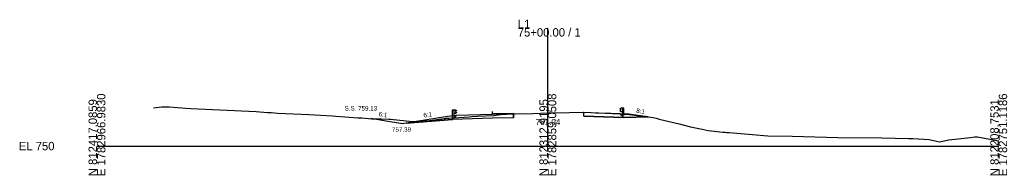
# Model space of a CAD drawing. Extents: x 5574 to 10203, y -10 to 9546.
# Drawn here: x 8574.3 to 8902.8, y 2990.3 to 3042 of the extents above; entities that cross this region are included whole.
import ezdxf

# ---------------------------------------------------------------- set-up
doc = ezdxf.new("R2010")
doc.units = 0
for name, color, linetype in [('Exist Cross Section Cell', 7, 'Continuous'), ('Exist XS Center Line Elevation Label', 7, 'Continuous'), ('Exist XS Ground Line', 7, 'Continuous'), ('Prop XS Ditch Slope Text', 7, 'Continuous'), ('Prop XS Ditch Standard Text', 7, 'Continuous'), ('Prop XS Dump Level', 7, 'Continuous'), ('Prop XS Earthwork Shape', 7, 'Continuous'), ('Prop XS EOT Tick Mark', 7, 'Continuous'), ('Prop XS Finish Grade', 7, 'Continuous'), ('Prop XS Finish Grade Earthwork', 7, 'Continuous'), ('Prop XS Finish Grade Paved Shoulder', 7, 'Continuous'), ('Prop XS Finish Grade Pavement', 7, 'Continuous'), ('Prop XS Guardrail', 7, 'Continuous'), ('Prop XS Hydro Typical Ditch Data', 7, 'Continuous'), ('Prop XS Pvmt Edge Slope', 7, 'Continuous'), ('Prop XS Side Slope Text', 7, 'Continuous'), ('Prop XS SS Elevation Text', 7, 'Continuous'), ('Prop XS Subgrade Earthwork', 7, 'Continuous'), ('Scratch_Level_3', 7, 'Continuous'), ('Scratch_Level_6', 7, 'Continuous')]:
    doc.layers.add(name, color=color, linetype=linetype)

msp = doc.modelspace()

# ---------------------------------------------------------------- linework, layer by layer
at = {"layer": 'Exist Cross Section Cell'}
for p, q in [((8750, 3000), (8750, 3039.22)), ((8600, 3000), (8750, 3000)), ((8750, 3000), (8900, 3000))]:
    msp.add_line(p, q, dxfattribs=at)
at = {"layer": 'Exist XS Ground Line'}
for p, q in [((8618.81, 3012.75), (8621.53, 3013.06)), ((8621.53, 3013.06), (8624.02, 3013.07)), ((8624.02, 3013.07), (8629.6, 3012.65)), ((8629.6, 3012.65), (8631.2, 3012.56)), ((8631.2, 3012.56), (8652.98, 3011.55)), ((8652.98, 3011.55), (8656.75, 3011.16)), ((8656.75, 3011.16), (8657.95, 3011.14)), ((8657.95, 3011.14), (8660.18, 3010.98)), ((8660.18, 3010.98), (8670.51, 3010.47)), ((8670.51, 3010.47), (8678.36, 3010.07)), ((8678.36, 3010.07), (8679.51, 3009.95)), ((8679.51, 3009.95), (8682.41, 3009.77)), ((8682.41, 3009.77), (8686.75, 3009.4)), ((8686.75, 3009.4), (8688.09, 3009.35)), ((8717.11, 3009.32), (8723.79, 3009.73)), ((8723.79, 3009.73), (8724.75, 3009.79)), ((8724.75, 3009.79), (8726.55, 3009.92)), ((8726.55, 3009.92), (8732.01, 3010.22)), ((8732.01, 3010.22), (8734.27, 3010.48)), ((8734.27, 3010.48), (8736.3, 3010.58)), ((8736.3, 3010.58), (8738.53, 3010.69)), ((8738.53, 3010.69), (8745, 3010.89)), ((8745, 3010.89), (8750, 3011.04)), ((8750, 3011.04), (8750.89, 3011.07)), ((8750.89, 3011.07), (8757.25, 3011.18)), ((8757.25, 3011.18), (8761.88, 3011.26)), ((8761.88, 3011.26), (8764.28, 3011.16)), ((8764.28, 3011.16), (8765.87, 3011.09)), ((8765.87, 3011.09), (8770.93, 3010.94)), ((8770.93, 3010.94), (8776.99, 3010.75)), ((8776.99, 3010.75), (8780.82, 3010.14)), ((8780.82, 3010.14), (8783.35, 3009.74)), ((8783.35, 3009.74), (8785.09, 3009.47)), ((8785.09, 3009.47), (8786.01, 3009.27)), ((8688.09, 3009.35), (8691.47, 3009.11)), ((8691.47, 3009.11), (8694.53, 3009.08)), ((8694.53, 3009.08), (8697.1, 3008.96)), ((8697.1, 3008.96), (8697.63, 3008.93)), ((8697.63, 3008.93), (8705.02, 3008.2)), ((8705.02, 3008.2), (8706.15, 3008.28)), ((8706.15, 3008.28), (8710.65, 3008.48)), ((8710.65, 3008.48), (8715.53, 3009.16)), ((8715.53, 3009.16), (8715.87, 3009.2)), ((8715.87, 3009.2), (8716.22, 3009.26)), ((8716.22, 3009.26), (8717.11, 3009.32)), ((8786.01, 3009.27), (8787, 3009)), ((8787, 3009), (8793.7, 3007.43)), ((8793.7, 3007.43), (8797.44, 3006.36)), ((8797.44, 3006.36), (8801.32, 3005.62)), ((8801.32, 3005.62), (8803.31, 3005.18)), ((8803.31, 3005.18), (8808.19, 3004.67)), ((8808.19, 3004.67), (8808.96, 3004.64)), ((8808.96, 3004.64), (8809.49, 3004.55)), ((8809.49, 3004.55), (8810.27, 3004.48)), ((8810.27, 3004.48), (8823.15, 3003.45)), ((8823.15, 3003.45), (8831.28, 3003.28)), ((8831.28, 3003.28), (8846.52, 3002.83)), ((8846.52, 3002.83), (8861.15, 3002.73)), ((8883.46, 3002.09), (8890.57, 3002.83)), ((8890.57, 3002.83), (8892, 3003.09)), ((8892, 3003.09), (8892.9, 3003.11)), ((8892.9, 3003.11), (8899.36, 3001.91)), ((8861.15, 3002.73), (8869.95, 3002.58)), ((8869.95, 3002.58), (8871.39, 3002.48)), ((8871.39, 3002.48), (8876.85, 3002.2)), ((8876.85, 3002.2), (8879.29, 3001.69)), ((8879.29, 3001.69), (8880.29, 3001.47)), ((8880.29, 3001.47), (8883.46, 3002.09)), ((8899.36, 3001.91), (8900, 3001.74))]:
    msp.add_line(p, q, dxfattribs=at)
at = {"layer": 'Prop XS Dump Level'}
msp.add_line((8738.55, 3010.81), (8731.59, 3010.68), dxfattribs=at)
at = {"layer": 'Prop XS Earthwork Shape'}
for points in [[(8736.3, 3010.58), (8738.54, 3010.69), (8738.54, 3009.44), (8731.63, 3009.24), (8718.31, 3008.84), (8702.91, 3007.61), (8701.59, 3007.39), (8695.59, 3008.39), (8691.16, 3009.13), (8691.47, 3009.11), (8694.53, 3009.08), (8697.1, 3008.96), (8697.63, 3008.93), (8705.02, 3008.2), (8706.15, 3008.28), (8710.65, 3008.48), (8715.53, 3009.16), (8715.87, 3009.2), (8716.22, 3009.26), (8717.11, 3009.32), (8723.79, 3009.73), (8724.75, 3009.79), (8726.55, 3009.92), (8732.01, 3010.22), (8734.27, 3010.48)], [(8764.28, 3011.16), (8765.87, 3011.09), (8770.93, 3010.94), (8776.99, 3010.75), (8780.82, 3010.14), (8783.35, 3009.74), (8775.3, 3009.48), (8762, 3010.01), (8762, 3011.26)]]:
    msp.add_lwpolyline(points, close=True, dxfattribs=at)
at = {"layer": 'Prop XS EOT Tick Mark'}
msp.add_line((8731.59, 3010.49), (8731.59, 3011.49), dxfattribs=at)
at = {"layer": 'Prop XS Finish Grade'}
for p, q in [((8716.59, 3009.89), (8702.91, 3007.61)), ((8719.59, 3010.13), (8716.59, 3009.89)), ((8774, 3010.78), (8777, 3010.54)), ((8777, 3010.54), (8783.35, 3009.74))]:
    msp.add_line(p, q, dxfattribs=at)
at = {"layer": 'Prop XS Finish Grade Earthwork'}
for p, q in [((8695.59, 3008.39), (8691.16, 3009.13)), ((8701.59, 3007.39), (8695.59, 3008.39)), ((8702.91, 3007.61), (8701.59, 3007.39))]:
    msp.add_line(p, q, dxfattribs=at)
at = {"layer": 'Prop XS Finish Grade Paved Shoulder'}
msp.add_line((8731.59, 3010.49), (8719.59, 3010.13), dxfattribs=at)
at = {"layer": 'Prop XS Finish Grade Pavement'}
for p, q in [((8738.54, 3010.69), (8731.59, 3010.49)), ((8762, 3011.26), (8774, 3010.78))]:
    msp.add_line(p, q, dxfattribs=at)
at = {"layer": 'Prop XS Guardrail'}
for p, q in [((8774.32, 3012.65), (8774.03, 3012.45)), ((8774.82, 3012.65), (8774.32, 3012.65)), ((8775.32, 3012.65), (8774.82, 3012.65)), ((8774.82, 3012.65), (8774.82, 3010.15)), ((8775.32, 3010.15), (8775.32, 3012.65)), ((8718.27, 3012.01), (8718.77, 3012.01)), ((8718.27, 3009.51), (8718.27, 3012.01)), ((8718.77, 3012.01), (8719.27, 3012.01)), ((8718.77, 3012.01), (8718.77, 3009.51)), ((8719.27, 3010.87), (8718.77, 3010.87)), ((8719.27, 3012.01), (8719.56, 3011.81)), ((8719.56, 3011.69), (8719.27, 3011.49)), ((8719.27, 3011.49), (8719.27, 3011.39)), ((8719.27, 3011.39), (8719.56, 3011.19)), ((8719.56, 3011.07), (8719.27, 3010.87)), ((8719.56, 3011.81), (8719.59, 3011.75)), ((8719.59, 3011.75), (8719.56, 3011.69)), ((8719.56, 3011.19), (8719.59, 3011.13)), ((8719.59, 3011.13), (8719.56, 3011.07)), ((8774.03, 3012.45), (8774, 3012.39)), ((8774, 3012.39), (8774.03, 3012.33)), ((8774.03, 3011.84), (8774, 3011.78)), ((8774, 3011.78), (8774.03, 3011.72)), ((8774.03, 3012.33), (8774.32, 3012.13)), ((8774.32, 3012.04), (8774.03, 3011.84)), ((8774.03, 3011.72), (8774.32, 3011.52)), ((8774.32, 3012.13), (8774.32, 3012.04)), ((8774.32, 3011.52), (8774.82, 3011.52))]:
    msp.add_line(p, q, dxfattribs=at)
at = {"layer": 'Prop XS Hydro Typical Ditch Data'}
for p, q in [((8695.59, 3008.39), (8691.16, 3009.13)), ((8701.59, 3007.39), (8695.59, 3008.39))]:
    msp.add_line(p, q, dxfattribs=at)
at = {"layer": 'Prop XS Pvmt Edge Slope'}
for p, q in [((8719.59, 3010.13), (8718.31, 3008.84)), ((8774, 3010.78), (8775.3, 3009.48))]:
    msp.add_line(p, q, dxfattribs=at)
at = {"layer": 'Prop XS Subgrade Earthwork'}
for p, q in [((8738.54, 3009.44), (8731.63, 3009.24)), ((8738.54, 3009.44), (8738.54, 3010.69)), ((8762, 3010.01), (8762, 3011.26)), ((8762, 3010.01), (8775.3, 3009.48)), ((8775.3, 3009.48), (8783.35, 3009.74)), ((8718.31, 3008.84), (8702.91, 3007.61)), ((8731.63, 3009.24), (8718.31, 3008.84))]:
    msp.add_line(p, q, dxfattribs=at)
at = {"layer": 'Scratch_Level_3'}
for p, q in [((8716.59, 3009.89), (8702.91, 3007.61)), ((8719.59, 3010.13), (8716.59, 3009.89)), ((8718.31, 3008.84), (8719.59, 3010.13)), ((8777, 3010.54), (8774, 3010.78)), ((8774, 3010.78), (8775.3, 3009.48)), ((8775.3, 3009.48), (8783.35, 3009.74)), ((8783.35, 3009.74), (8777, 3010.54)), ((8702.91, 3007.61), (8718.31, 3008.84))]:
    msp.add_line(p, q, dxfattribs=at)
at = {"layer": 'Scratch_Level_6'}
for points in [[(8738.54, 3009.44), (8731.63, 3009.24), (8718.31, 3008.84), (8702.91, 3007.61), (8707.19, 3008.33), (8710.65, 3008.48), (8715.53, 3009.16), (8715.87, 3009.2), (8716.22, 3009.26), (8717.11, 3009.32), (8723.79, 3009.73), (8724.75, 3009.79), (8726.55, 3009.92), (8732.01, 3010.22), (8734.27, 3010.48), (8736.3, 3010.58), (8738.54, 3010.69)], [(8766.91, 3011.06), (8774, 3010.78), (8777, 3010.54), (8783.35, 3009.74), (8775.3, 3009.48), (8762, 3010.01), (8762, 3011.26), (8764.28, 3011.16), (8765.87, 3011.09)]]:
    msp.add_lwpolyline(points, close=True, dxfattribs=at)

# ---------------------------------------------------------------- texts
at = {"layer": 'Exist Cross Section Cell'}
for s, p in [('75+00.00 / 1', (8740, 3036.42)), ('L1', (8740, 3039.22)), ('EL 750', (8574, 2998.6))]:
    msp.add_text(s, height=2.8, dxfattribs=at).set_placement(p)
for s, p in [('E 1782966.9830', (8602.8, 2990)), ('E 1782859.0508', (8752.8, 2990)), ('E 1782751.1186', (8902.8, 2990)), ('N 812417.0859', (8600, 2990)), ('N 812312.9195', (8750, 2990)), ('N 812208.7531', (8900, 2990))]:
    msp.add_text(s, height=2.8, rotation=90, dxfattribs=at).set_placement(p)
at = {"layer": 'Exist XS Center Line Elevation Label'}
msp.add_text('761.04', height=2, dxfattribs=at).set_placement((8745.96, 3007.04))
at = {"layer": 'Prop XS Ditch Slope Text'}
for s, rotation, p in [('6:1', 9.4623, (8708.73, 3009.47)), ('8:1', 352.8766, (8779.34, 3011.08))]:
    msp.add_text(s, height=1.5, rotation=rotation, dxfattribs=at).set_placement(p)
at = {"layer": 'Prop XS Ditch Standard Text'}
msp.add_text('757.39', height=1.5, dxfattribs=at).set_placement((8698.15, 3004.78))
at = {"layer": 'Prop XS Dump Level'}
for s, height, p in [('Case4', 0.04, (8719.59, 3009.69)), ('Eop', 0.3, (8738.54, 3010.39))]:
    msp.add_text(s, height=height, dxfattribs=at).set_placement(p)
at = {"layer": 'Prop XS Side Slope Text'}
msp.add_text('6:1', height=1.5, rotation=350.5377, dxfattribs=at).set_placement((8693.61, 3009.99))
at = {"layer": 'Prop XS SS Elevation Text'}
msp.add_text('S.S. 759.13', height=1.5, dxfattribs=at).set_placement((8682.39, 3011.82))

doc.saveas('drawing.dxf')
